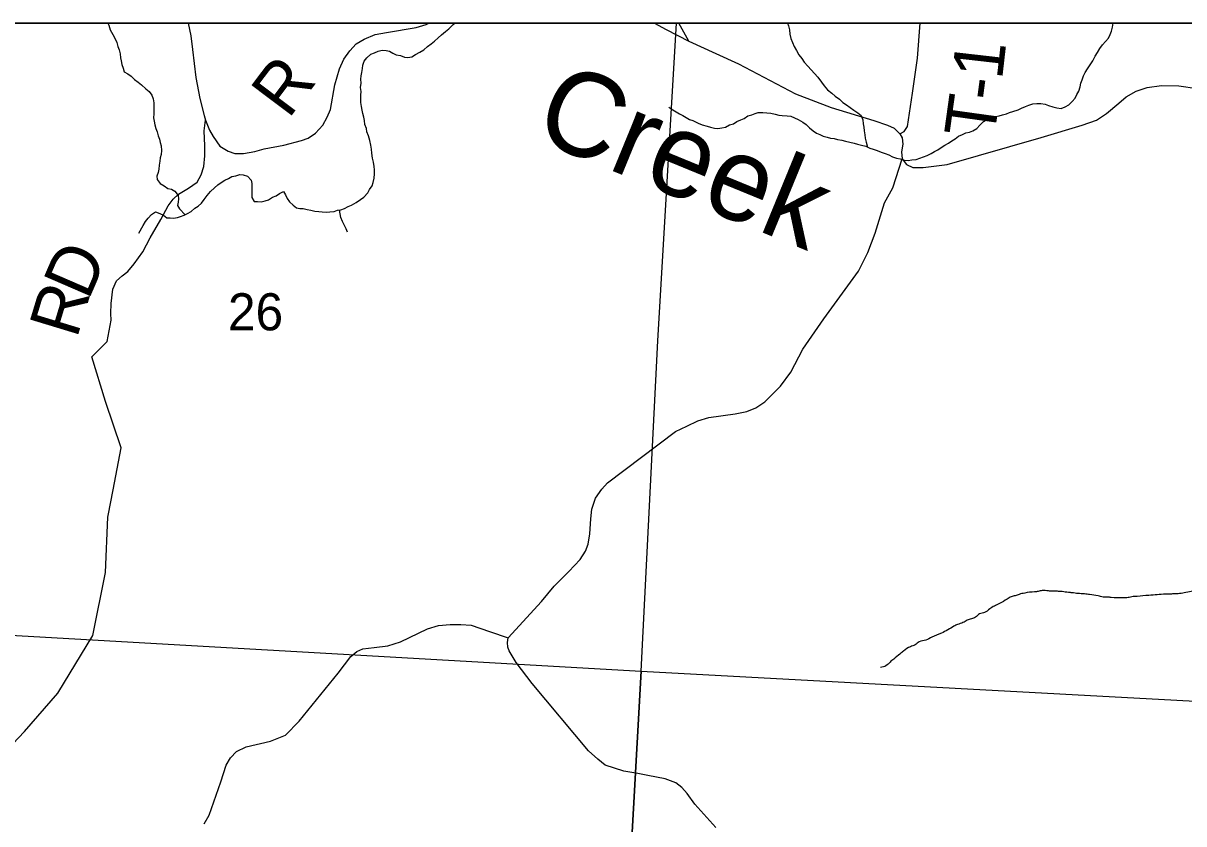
# Model space of a CAD drawing. Extents: x -20.2 to 34, y 0 to 22.
# Drawn here: x 3.126 to 4.435, y 19.997 to 20.9 of the extents above; entities that cross this region are included whole.
import ezdxf

# ---------------------------------------------------------------- set-up
doc = ezdxf.new("R2010")
doc.units = 0
for name, color, linetype in [('Default', 7, 'Continuous'), ('GM_X_County_Road', 7, 'Continuous'), ('GM_X_County_Road_Text', 7, 'Continuous'), ('GM_X_Minor_River', 7, 'Continuous'), ('GM_X_Minor_River_Text', 7, 'Continuous'), ('GM_X_Section', 7, 'Continuous'), ('GM_X_Section_Text', 7, 'Continuous'), ('GM_X_Township_Road', 7, 'Continuous'), ('GM_X_Township_Road_Text', 7, 'Continuous'), ('SH_Cut_Line', 7, 'Continuous'), ('SH_Data', 7, 'Continuous')]:
    doc.layers.add(name, color=color, linetype=linetype)

msp = doc.modelspace()

# ---------------------------------------------------------------- linework, layer by layer
at = {"layer": 'Default'}
for points in [[(8.1508, 20.9), (2.1, 20.9), (2.1, 19.2514), (2.9253, 19.1951), (4.084, 19.1299), (4.129, 19.1285), (4.5, 19.1063), (4.5753, 19.1032), (5.0716, 19.0751), (5.6168, 19.0426), (5.628, 19.0419), (5.9006, 19.026), (6.5332, 18.9927), (7.3871, 18.9465), (7.5395, 18.9382), (7.8072, 18.9199), (8.043, 18.9097), (8.0485, 19.0914), (8.0709, 19.4522), (8.1316, 20.5548)], [(3.8628, 20.9), (2.8035, 20.9), (2.7621, 20.2295), (3.8229, 20.1691), (3.8415, 20.5416)]]:
    msp.add_lwpolyline(points, close=True, dxfattribs=at)
at = {"layer": 'GM_X_County_Road'}
for points in [[(3.3118, 20.9), (3.3148, 20.8858), (3.3167, 20.8703), (3.3205, 20.8389), (3.3249, 20.8152), (3.3299, 20.7958), (3.3312, 20.7908), (3.336, 20.7794), (3.3399, 20.7722), (3.3476, 20.7612), (3.3568, 20.7555), (3.3645, 20.753), (3.3744, 20.753), (3.387, 20.7553), (3.3974, 20.7581), (3.4196, 20.7626), (3.4398, 20.7676), (3.4471, 20.7704), (3.4555, 20.776), (3.4637, 20.7851), (3.4687, 20.794), (3.4724, 20.8027), (3.4774, 20.8304), (3.4824, 20.8487), (3.4876, 20.8596), (3.4942, 20.8687), (3.5015, 20.8767), (3.5104, 20.8819), (3.5229, 20.8871), (3.5354, 20.8896), (3.5691, 20.8953), (3.5803, 20.8985), (3.5833, 20.9)], [(3.838, 20.9), (3.8512, 20.8928), (3.8767, 20.8799), (3.9072, 20.866), (3.9327, 20.8543), (3.997, 20.8202), (4.0371, 20.805), (4.0852, 20.7904), (4.1007, 20.7849), (4.1084, 20.7817), (4.1147, 20.7753), (4.1173, 20.7706), (4.1182, 20.7637), (4.1166, 20.7549), (4.1171, 20.7469), (4.1223, 20.7405), (4.1294, 20.7371), (4.1408, 20.7373), (4.1679, 20.7405), (4.2742, 20.7712), (4.3202, 20.7851), (4.3365, 20.7908), (4.3479, 20.7981), (4.3618, 20.8097), (4.37, 20.8168), (4.3814, 20.8234), (4.3937, 20.8275), (4.4099, 20.8298), (4.4294, 20.8295), (4.4499, 20.8263)], [(3.9072, 19.9927), (3.8833, 20.0191), (3.8749, 20.0309), (3.8687, 20.0377), (3.8621, 20.043), (3.8498, 20.0475), (3.8302, 20.0514), (3.8191, 20.0535), (3.8034, 20.0562), (3.7824, 20.0629), (3.774, 20.0698), (3.7633, 20.079), (3.7, 20.1552), (3.682, 20.1789), (3.6741, 20.1919), (3.6726, 20.196), (3.672, 20.2012), (3.6727, 20.2067), (3.7105, 20.2476), (3.7248, 20.265), (3.7412, 20.2816), (3.7542, 20.295), (3.7601, 20.3043), (3.7629, 20.3121), (3.7651, 20.3241), (3.766, 20.341), (3.7672, 20.3519), (3.7713, 20.364), (3.7783, 20.3742), (3.7847, 20.3815), (3.8617, 20.4393), (3.8742, 20.4455), (3.8867, 20.4514), (3.8992, 20.455), (3.9288, 20.4594), (3.942, 20.4621), (3.9523, 20.4662), (3.9625, 20.473), (3.98, 20.4906), (3.9917, 20.5065), (4.0051, 20.5322), (4.0288, 20.5664), (4.0681, 20.6201), (4.0784, 20.6413), (4.0868, 20.6631), (4.0973, 20.6975), (4.1066, 20.7143), (4.1171, 20.7469)]]:
    msp.add_lwpolyline(points, dxfattribs=at)
at = {"layer": 'GM_X_Minor_River'}
for points in [[(3.2213, 20.9), (3.2222, 20.8978), (3.2238, 20.8925), (3.2269, 20.8872), (3.2296, 20.8823), (3.2312, 20.8782), (3.2323, 20.8736), (3.2339, 20.8699)], [(3.5071, 20.8405), (3.5078, 20.8443), (3.5085, 20.8489), (3.5088, 20.8527), (3.5103, 20.8572), (3.5133, 20.8611), (3.5178, 20.8649), (3.5219, 20.8665), (3.5261, 20.8684), (3.5306, 20.8696), (3.5352, 20.8692), (3.539, 20.8685), (3.5428, 20.8663), (3.5466, 20.8644), (3.5512, 20.8637), (3.5557, 20.8618), (3.5595, 20.8615), (3.5641, 20.8619), (3.5682, 20.8646), (3.5731, 20.8673), (3.5776, 20.87), (3.5818, 20.8738), (3.5859, 20.8769), (3.5897, 20.8796), (3.5938, 20.8834), (3.5975, 20.8869), (3.602, 20.8907), (3.6058, 20.8938), (3.6107, 20.8984), (3.6125, 20.9)], [(3.9879, 20.9), (3.9889, 20.897), (3.9901, 20.8924), (3.9905, 20.8875), (3.9917, 20.8826), (3.9937, 20.8784), (3.9956, 20.8739), (3.9979, 20.8694), (4.0006, 20.8644), (4.0041, 20.8603), (4.0068, 20.8562), (4.011, 20.8516), (4.0148, 20.8475), (4.0183, 20.8434), (4.0221, 20.8392), (4.0263, 20.8336), (4.0294, 20.8294), (4.0332, 20.8249), (4.0378, 20.8212), (4.0417, 20.8178), (4.0466, 20.8144), (4.0504, 20.8106), (4.0543, 20.808), (4.0588, 20.805), (4.0627, 20.802), (4.0672, 20.799), (4.0711, 20.7957), (4.073, 20.7911), (4.0734, 20.7866), (4.0742, 20.7828), (4.0743, 20.7786), (4.0751, 20.7741), (4.0755, 20.7703), (4.0767, 20.7657), (4.0783, 20.7602)], [(4.2786, 20.8086), (4.2824, 20.8071), (4.2874, 20.8056), (4.2919, 20.8045), (4.2965, 20.8038), (4.301, 20.8058), (4.3052, 20.8081), (4.3089, 20.8115), (4.3123, 20.8153), (4.3145, 20.8195), (4.3164, 20.8234), (4.3182, 20.8283), (4.3189, 20.8325), (4.3204, 20.8363), (4.3219, 20.8405), (4.3237, 20.8443), (4.3263, 20.8485), (4.3293, 20.8531), (4.3323, 20.8577), (4.3349, 20.863), (4.3375, 20.8668), (4.3401, 20.8714), (4.3431, 20.8756), (4.3465, 20.8794), (4.3499, 20.8832), (4.3521, 20.8871), (4.3536, 20.8909), (4.3547, 20.8954), (4.3554, 20.9), (4.3554, 20.9)], [(3.2339, 20.8699), (3.2351, 20.8653), (3.2355, 20.8611), (3.2363, 20.8574), (3.2371, 20.8536), (3.2383, 20.8494), (3.2395, 20.8452), (3.2436, 20.843), (3.2475, 20.8404), (3.2513, 20.8366), (3.2555, 20.8336), (3.2593, 20.8303), (3.2639, 20.8261), (3.2677, 20.8231), (3.2708, 20.819), (3.2723, 20.8148), (3.2732, 20.8103), (3.2732, 20.8065), (3.2732, 20.8015), (3.2729, 20.7977), (3.2726, 20.7932), (3.2734, 20.7894), (3.2742, 20.7852), (3.2753, 20.7814), (3.2769, 20.7773), (3.2781, 20.7731), (3.2796, 20.7693), (3.2804, 20.7656), (3.2812, 20.7618), (3.2817, 20.7565), (3.2813, 20.7519), (3.2802, 20.7481), (3.2799, 20.7443), (3.2792, 20.7397), (3.2788, 20.7352), (3.2781, 20.7314), (3.2766, 20.7276), (3.2767, 20.7238), (3.2801, 20.7193), (3.2847, 20.7167), (3.2889, 20.7137), (3.2931, 20.7126), (3.2969, 20.7107), (3.3007, 20.7058), (3.3009, 20.7019), (3.3004, 20.6982), (3.2997, 20.6944), (3.302, 20.6906), (3.3085, 20.684)], [(3.2561, 20.6632), (3.2609, 20.6717), (3.2635, 20.6762), (3.2665, 20.6801), (3.2703, 20.6843), (3.2748, 20.6873), (3.2797, 20.6855), (3.2839, 20.6833), (3.2877, 20.6806), (3.2915, 20.6803), (3.2953, 20.6799), (3.2997, 20.6807), (3.3032, 20.6819), (3.3074, 20.6835), (3.3112, 20.6854), (3.3153, 20.6877), (3.3194, 20.6912), (3.3232, 20.6935), (3.327, 20.6969), (3.33, 20.7011), (3.3333, 20.7057), (3.3371, 20.7103), (3.3416, 20.7141), (3.3453, 20.7176), (3.3491, 20.7203), (3.3532, 20.723), (3.3574, 20.7249), (3.3612, 20.7272), (3.3657, 20.728), (3.3702, 20.7292), (3.374, 20.7289), (3.3786, 20.7274), (3.3828, 20.7229), (3.3836, 20.7191), (3.3836, 20.7153), (3.3837, 20.7107), (3.3837, 20.7069), (3.3838, 20.7032), (3.3861, 20.699), (3.3902, 20.6987), (3.394, 20.6983), (3.3986, 20.6995), (3.4023, 20.7007), (3.4069, 20.7037), (3.411, 20.7053), (3.4148, 20.708), (3.4193, 20.7103), (3.4216, 20.7062), (3.4235, 20.7024), (3.4262, 20.6986), (3.4301, 20.6949), (3.4339, 20.6919), (3.4377, 20.6908), (3.4415, 20.6908), (3.446, 20.6897), (3.4502, 20.689), (3.4548, 20.6879), (3.4593, 20.6875), (3.4631, 20.6872), (3.4677, 20.6869), (3.4718, 20.6873), (3.4764, 20.6877), (3.4802, 20.6889), (3.4839, 20.6893), (3.4881, 20.6908), (3.4922, 20.6932), (3.496, 20.6947), (3.5013, 20.6978), (3.5062, 20.7013), (3.5099, 20.7039), (3.5144, 20.7085), (3.5163, 20.7124), (3.5193, 20.7166), (3.5204, 20.7204), (3.5215, 20.7253), (3.5222, 20.7302), (3.5221, 20.7344), (3.5217, 20.7382), (3.5209, 20.7431), (3.5197, 20.7477), (3.5189, 20.7534), (3.5185, 20.7579), (3.5177, 20.7625), (3.5169, 20.7678), (3.5153, 20.7731), (3.5134, 20.7776), (3.513, 20.7814), (3.511, 20.7859), (3.5106, 20.7901), (3.5098, 20.7939), (3.509, 20.798), (3.5082, 20.8018), (3.5074, 20.806), (3.5066, 20.8105), (3.5066, 20.8147), (3.5065, 20.8189), (3.5068, 20.8231), (3.5064, 20.8276), (3.5068, 20.8322), (3.5067, 20.8367), (3.5071, 20.8405)], [(3.8542, 20.8054), (3.8584, 20.8024), (3.8622, 20.8002), (3.866, 20.7979), (3.8698, 20.7957), (3.8736, 20.7935), (3.8774, 20.7912), (3.8812, 20.7901), (3.887, 20.7871), (3.8915, 20.7853), (3.8972, 20.7838), (3.901, 20.7827), (3.9056, 20.7816), (3.9094, 20.7813), (3.9139, 20.7821), (3.9181, 20.7829), (3.9226, 20.7852), (3.9271, 20.7864), (3.9309, 20.7891), (3.9354, 20.791), (3.9392, 20.7925), (3.943, 20.7956), (3.9475, 20.7968), (3.9513, 20.798), (3.955, 20.7991), (3.96, 20.7992), (3.9645, 20.7988), (3.9691, 20.7985), (3.974, 20.7974), (3.9782, 20.7963), (3.982, 20.796), (3.9877, 20.7956), (3.9915, 20.7953), (3.9957, 20.7934), (3.9999, 20.7912), (4.0052, 20.7882), (4.009, 20.7856), (4.0128, 20.7818), (4.0167, 20.7785), (4.0205, 20.7758), (4.0243, 20.7744), (4.0281, 20.7725), (4.0326, 20.7714), (4.0364, 20.7703), (4.0406, 20.77), (4.0444, 20.7689), (4.0494, 20.7681), (4.0535, 20.767), (4.0581, 20.7659), (4.063, 20.7645), (4.0668, 20.7637), (4.0714, 20.7623), (4.0763, 20.7612), (4.0809, 20.7589), (4.0847, 20.7578), (4.0889, 20.7564), (4.0935, 20.7545), (4.098, 20.753), (4.1022, 20.7516), (4.1064, 20.7493), (4.111, 20.7478), (4.1151, 20.7471), (4.1197, 20.7456), (4.1242, 20.7453), (4.128, 20.7457), (4.133, 20.7461), (4.1371, 20.7477), (4.1413, 20.7493), (4.1454, 20.7508), (4.1499, 20.7531), (4.1537, 20.7554), (4.1575, 20.757), (4.1612, 20.7597), (4.1654, 20.7624), (4.1695, 20.7647), (4.1733, 20.7674), (4.1771, 20.7697), (4.1808, 20.7724), (4.1853, 20.7743), (4.1891, 20.7763), (4.1933, 20.7771), (4.1971, 20.7786), (4.2016, 20.7813), (4.2049, 20.7851), (4.2091, 20.789), (4.2136, 20.7917), (4.2181, 20.7932), (4.2227, 20.7948), (4.2268, 20.7956), (4.2306, 20.7968), (4.2348, 20.7979), (4.2385, 20.7991), (4.2423, 20.8003), (4.248, 20.8022), (4.2518, 20.8042), (4.2563, 20.8061), (4.2601, 20.8077), (4.2646, 20.8092), (4.2691, 20.8096), (4.2737, 20.8093), (4.2786, 20.8086)], [(3.4914, 20.6643), (3.4902, 20.6681), (3.4879, 20.6726), (3.486, 20.6764), (3.484, 20.6809), (3.4827, 20.6891)]]:
    msp.add_lwpolyline(points, dxfattribs=at)
msp.add_spline([(4.52, 20.2524), (4.5136, 20.2524), (4.5079, 20.2532), (4.5015, 20.2544), (4.4901, 20.2564), (4.4837, 20.258), (4.4787, 20.2588), (4.4742, 20.2588), (4.4662, 20.2596), (4.4503, 20.2597), (4.4453, 20.2594), (4.4374, 20.2576), (4.4301, 20.2565), (4.4237, 20.2562), (4.4184, 20.2558), (4.4142, 20.2558), (4.4051, 20.2552), (4.3956, 20.2545), (4.3823, 20.2534), (4.3778, 20.2531), (4.3721, 20.252), (4.366, 20.2517), (4.3531, 20.2521), (4.3489, 20.2526), (4.344, 20.2526), (4.3383, 20.2538), (4.3288, 20.2554), (4.3231, 20.2562), (4.3155, 20.2566), (4.3091, 20.2574), (4.3049, 20.2578), (4.2977, 20.2587), (4.2924, 20.2591), (4.2879, 20.2591), (4.2822, 20.2595), (4.2753, 20.26), (4.2708, 20.2589), (4.2666, 20.2585), (4.2556, 20.2571), (4.2491, 20.2556), (4.2446, 20.2541), (4.2404, 20.253), (4.2358, 20.2504), (4.227, 20.2452), (4.216, 20.2392), (4.2103, 20.235), (4.2046, 20.2336), (4.2, 20.2298), (4.1954, 20.2279), (4.1905, 20.2265), (4.1859, 20.2238), (4.1798, 20.2216), (4.1756, 20.2197), (4.1688, 20.2156), (4.1615, 20.2119), (4.1509, 20.2074), (4.144, 20.204), (4.1364, 20.2022), (4.1318, 20.1988), (4.1265, 20.1966), (4.1189, 20.1917), (4.1147, 20.1883), (4.1078, 20.1827), (4.1036, 20.1793), (4.099, 20.1751), (4.0929, 20.1733)], degree=3, dxfattribs=at)
at = {"layer": 'GM_X_Section'}
for points in [[(3.8229, 20.1691), (3.7661, 19.1519), (2.7046, 19.2077), (2.7621, 20.2295)], [(3.8229, 20.1691), (4.8996, 20.1107), (4.8379, 19.0901), (3.7661, 19.1519)]]:
    msp.add_lwpolyline(points, close=True, dxfattribs=at)
at = {"layer": 'GM_X_Township_Road'}
msp.add_line((3.8767, 20.8799), (3.8654, 20.9), dxfattribs=at)
for points in [[(4.1147, 20.7753), (4.1195, 20.7778), (4.1232, 20.7833), (4.129, 20.8211), (4.1344, 20.8606), (4.1377, 20.9)], [(3.2271, 20.3734), (3.2363, 20.4211), (3.2185, 20.4732), (3.2031, 20.5236), (3.2205, 20.541), (3.2249, 20.5648), (3.2247, 20.5724), (3.2249, 20.5836), (3.227, 20.6001), (3.2311, 20.6095), (3.2372, 20.6149), (3.2439, 20.6198), (3.251, 20.6285), (3.2606, 20.642), (3.2689, 20.6578), (3.2808, 20.6786), (3.2892, 20.694), (3.2947, 20.7016), (3.3009, 20.7073), (3.312, 20.7138), (3.322, 20.7208), (3.3266, 20.729), (3.3296, 20.7382), (3.3307, 20.7503), (3.3305, 20.7616), (3.3298, 20.7785), (3.3312, 20.7908)], [(2.971, 19.502), (2.9721, 19.5068), (2.988, 19.5479), (2.9923, 19.5921), (3.0168, 19.6706), (3.0287, 19.752), (3.0262, 19.8146), (3.0241, 19.9038), (3.0367, 19.975), (3.0678, 20.0386), (3.1273, 20.1008), (3.1647, 20.1442), (3.2042, 20.2092), (3.2187, 20.2804), (3.2213, 20.3428), (3.2214, 20.3445), (3.2271, 20.3734)], [(3.33, 19.9966), (3.3354, 20.0064), (3.3486, 20.0443), (3.3546, 20.0629), (3.3597, 20.0712), (3.3664, 20.0783), (3.3772, 20.0838), (3.4046, 20.0902), (3.4217, 20.0967), (3.437, 20.1126), (3.4811, 20.1669), (3.4955, 20.1855), (3.5022, 20.1912), (3.5087, 20.1943), (3.5215, 20.1956), (3.5369, 20.1977), (3.5513, 20.2022), (3.5817, 20.2167), (3.5943, 20.2206), (3.6075, 20.2215), (3.6193, 20.2215), (3.6309, 20.2208), (3.6518, 20.2137), (3.6727, 20.2067)]]:
    msp.add_lwpolyline(points, dxfattribs=at)
at = {"layer": 'SH_Cut_Line'}
msp.add_lwpolyline([(5.7735, 14.1), (8.9, 14.1), (8.9, 20.9), (2.1, 20.9), (2.1, 14.1), (5.3953, 14.1), (5.7268, 14.1076)], close=True, dxfattribs=at)
at = {"layer": 'SH_Data'}
msp.add_line((2.1, 20.9), (8.9, 20.9), dxfattribs=at)

# ---------------------------------------------------------------- texts
at = {"layer": 'GM_X_County_Road_Text'}
msp.add_text('R', height=0.0568, rotation=53.0435, dxfattribs=at).set_placement((3.4249, 20.7909))
at = {"layer": 'GM_X_Minor_River_Text'}
msp.add_text('Creek', height=0.0947, rotation=337.6849, dxfattribs=at).set_placement((3.6982, 20.7712))
at = {"layer": 'GM_X_Section_Text'}
msp.add_text('26', height=0.04186, rotation=0, dxfattribs=at).set_placement((3.3567, 20.5535))
at = {"layer": 'GM_X_Township_Road_Text'}
for s, rotation, p in [('1', 83.4887, (4.2299, 20.8352)), ('-', 82.4323, (4.2267, 20.811)), ('T', 82.0978, (4.2208, 20.7685)), ('D', 66.5742, (3.1991, 20.5863)), ('R', 73.0981, (3.1861, 20.5432))]:
    msp.add_text(s, height=0.0568, rotation=rotation, dxfattribs=at).set_placement(p)

doc.saveas('drawing.dxf')
